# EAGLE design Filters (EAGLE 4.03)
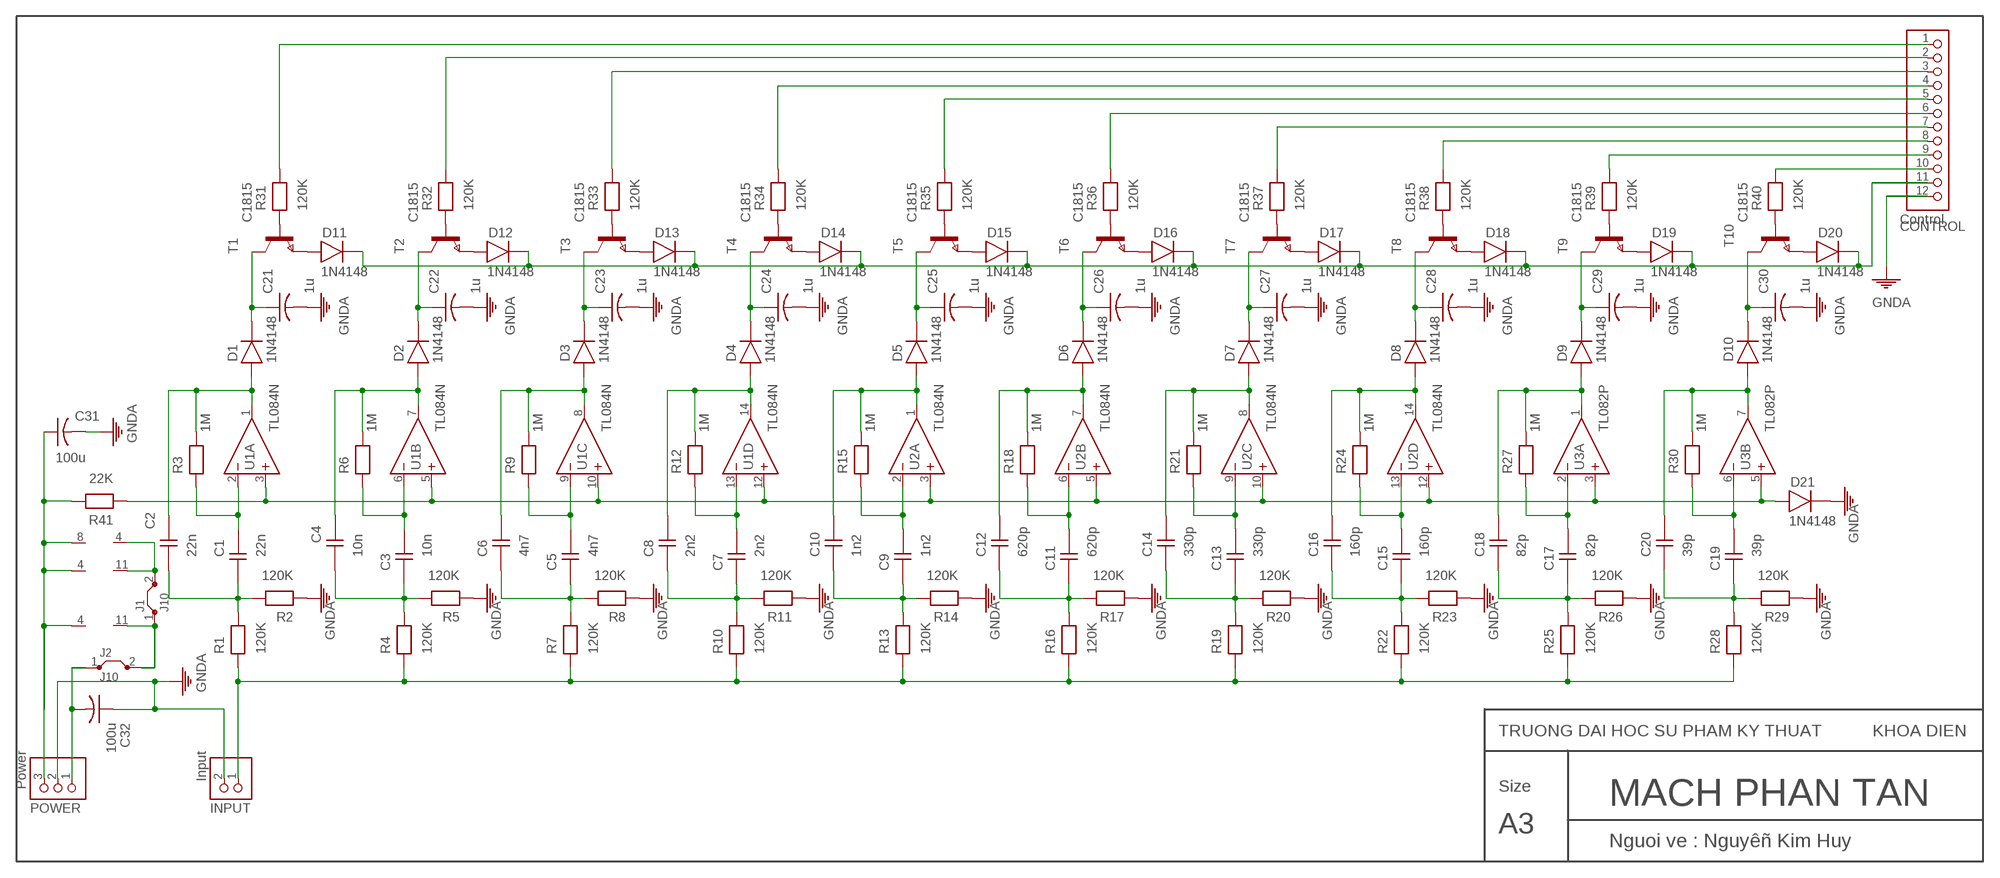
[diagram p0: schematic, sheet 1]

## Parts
C1  22n  CAPNP-5  [C-5]
C2  22n  CAPNP-5  [C-5]
C3  10n  CAPNP-5  [C-5]
C4  10n  CAPNP-5  [C-5]
C5  4n7  CAPNP-5  [C-5]
C6  4n7  CAPNP-5  [C-5]
C7  2n2  CAPNP-5  [C-5]
C8  2n2  CAPNP-5  [C-5]
C9  1n2  CAPNP-5  [C-5]
C10  1n2  CAPNP-5  [C-5]
C11  620p  CAPNP-5  [C-5]
C12  620p  CAPNP-5  [C-5]
C13  330p  CAPNP-5  [C-5]
C14  330p  CAPNP-5  [C-5]
C15  160p  CAPNP-5  [C-5]
C16  160p  CAPNP-5  [C-5]
C17  82p  CAPNP-5  [C-5]
C18  82p  CAPNP-5  [C-5]
C19  39p  CAPNP-5  [C-5]
C20  39p  CAPNP-5  [C-5]
C21  1u  CAP-5  [C-5]
C22  1u  CAP-5  [C-5]
C23  1u  CAP-5  [C-5]
C24  1u  CAP-5  [C-5]
C25  1u  CAP-5  [C-5]
C26  1u  CAP-5  [C-5]
C27  1u  CAP-5  [C-5]
C28  1u  CAP-5  [C-5]
C29  1u  CAP-5  [C-5]
C30  1u  CAP-5  [C-5]
C31  100u  CAP-5@2  [C-5@2]
C32  100u  CAP-5@2  [C-5@2]
CONTROL  Control  PINHD-1X12  [1X12]
D1  1N4148  DIODE-10  [D-10]
D2  1N4148  DIODE-10  [D-10]
D3  1N4148  DIODE-10  [D-10]
D4  1N4148  DIODE-10  [D-10]
D5  1N4148  DIODE-10  [D-10]
D6  1N4148  DIODE-10  [D-10]
D7  1N4148  DIODE-10  [D-10]
D8  1N4148  DIODE-10  [D-10]
D9  1N4148  DIODE-10  [D-10]
D10  1N4148  DIODE-10  [D-10]
D11  1N4148  DIODE-10  [D-10]
D12  1N4148  DIODE-10  [D-10]
D13  1N4148  DIODE-10  [D-10]
D14  1N4148  DIODE-10  [D-10]
D15  1N4148  DIODE-10  [D-10]
D16  1N4148  DIODE-10  [D-10]
D17  1N4148  DIODE-10  [D-10]
D18  1N4148  DIODE-10  [D-10]
D19  1N4148  DIODE-10  [D-10]
D20  1N4148  DIODE-10  [D-10]
D21  1N4148  DIODE-10  [D-10]
INPUT  Input  PINHD-1X2  [1X02]
J1  J10  [07]
J2  J10  [07]
POWER  Power  PINHD-1X3  [1X03]
R1  120K  RESEU-10  [R-10]
R2  120K  RESEU-10  [R-10]
R3  1M  RESEU-10  [R-10]
R4  120K  RESEU-10  [R-10]
R5  120K  RESEU-10  [R-10]
R6  1M  RESEU-10  [R-10]
R7  120K  RESEU-10  [R-10]
R8  120K  RESEU-10  [R-10]
R9  1M  RESEU-10  [R-10]
R10  120K  RESEU-10  [R-10]
R11  120K  RESEU-10  [R-10]
R12  1M  RESEU-10  [R-10]
R13  120K  RESEU-10  [R-10]
R14  120K  RESEU-10  [R-10]
R15  1M  RESEU-10  [R-10]
R16  120K  RESEU-10  [R-10]
R17  120K  RESEU-10  [R-10]
R18  1M  RESEU-10  [R-10]
R19  120K  RESEU-10  [R-10]
R20  120K  RESEU-10  [R-10]
R21  1M  RESEU-10  [R-10]
R22  120K  RESEU-10  [R-10]
R23  120K  RESEU-10  [R-10]
R24  1M  RESEU-10  [R-10]
R25  120K  RESEU-10  [R-10]
R26  120K  RESEU-10  [R-10]
R27  1M  RESEU-10  [R-10]
R28  120K  RESEU-10  [R-10]
R29  120K  RESEU-10  [R-10]
R30  1M  RESEU-10  [R-10]
R31  120K  RESEU-10  [R-10]
R32  120K  RESEU-10  [R-10]
R33  120K  RESEU-10  [R-10]
R34  120K  RESEU-10  [R-10]
R35  120K  RESEU-10  [R-10]
R36  120K  RESEU-10  [R-10]
R37  120K  RESEU-10  [R-10]
R38  120K  RESEU-10  [R-10]
R39  120K  RESEU-10  [R-10]
R40  120K  RESEU-10  [R-10]
R41  22K  RESEU-10  [R-10]
T1  C1815  [TO-92B]
T2  C1815  [TO-92B]
T3  C1815  [TO-92B]
T4  C1815  [TO-92B]
T5  C1815  [TO-92B]
T6  C1815  [TO-92B]
T7  C1815  [TO-92B]
T8  C1815  [TO-92B]
T9  C1815  [TO-92B]
T10  C1815  [TO-92B]
U1  TL084N  [DIL-14]
U2  TL084N  [DIL-14]
U3  TL082P  [DIL-08]

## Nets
GNDA: C21.2 C22.2 C23.2 C24.2 C25.2 C26.2 C27.2 C28.2 C29.2 C30.2 C31.2 C32.1 CONTROL.12 D21.2(K) INPUT.2 POWER.2 R2.1 R5.1 R8.1 R11.1 R14.1 R17.1 R20.1 R23.1 R26.1 R29.1
N$1: C1.2 R3.1 U1.2(A:-IN)
N$2: C1.1 C2.1 R1.2 R2.2
N$3: C3.1 C4.1 R4.2 R5.2
N$4: C9.2 R15.1 U2.2(A:-IN)
N$5: C2.2 D1.1(A) R3.2 U1.1(A:OUT)
N$6: C3.2 R6.1 U1.6(B:-IN)
N$7: C9.1 C10.1 R13.2 R14.2
N$8: C4.2 D2.1(A) R6.2 U1.7(B:OUT)
N$9: D11.1(A) T1.3(E)
N$10: INPUT.1 R1.1 R4.1 R7.1 R10.1 R13.1 R16.1 R19.1 R22.1 R25.1 R28.1
N$11: D21.1(A) R41.1 U1.3(A:+IN) U1.5(B:+IN) U1.10(C:+IN) U1.12(D:+IN) U2.3(A:+IN) U2.5(B:+IN) U2.10(C:+IN) U2.12(D:+IN) U3.3(A:+IN) U3.5(B:+IN)
N$12: C6.2 D3.1(A) R9.2 U1.8(C:OUT)
N$13: C10.2 D5.1(A) R15.2 U2.1(A:OUT)
N$14: C5.2 R9.1 U1.9(C:-IN)
N$15: C19.2 R30.1 U3.6(B:-IN)
N$16: C5.1 C6.1 R7.2 R8.2
N$17: C11.1 C12.1 R16.2 R17.2
N$18: C7.1 C8.1 R10.2 R11.2
N$19: C21.1 D1.2(K) T1.2(C)
N$20: C7.2 R12.1 U1.13(D:-IN)
N$21: C11.2 R18.1 U2.6(B:-IN)
N$22: C8.2 D4.1(A) R12.2 U1.14(D:OUT)
N$23: C20.2 D10.1(A) R30.2 U3.7(B:OUT)
N$24: C12.2 D6.1(A) R18.2 U2.7(B:OUT)
N$25: C22.1 D2.2(K) T2.2(C)
N$26: C13.1 C14.1 R19.2 R20.2
N$27: C23.1 D3.2(K) T3.2(C)
N$28: C13.2 R21.1 U2.9(C:-IN)
N$29: C24.1 D4.2(K) T4.2(C)
N$30: C14.2 D7.1(A) R21.2 U2.8(C:OUT)
N$31: C25.1 D5.2(K) T5.2(C)
N$32: C19.1 C20.1 R28.2 R29.2
N$33: C15.1 C16.1 R22.2 R23.2
N$34: C26.1 D6.2(K) T6.2(C)
N$35: C15.2 R24.1 U2.13(D:-IN)
N$36: C27.1 D7.2(K) T7.2(C)
N$37: C16.2 D8.1(A) R24.2 U2.14(D:OUT)
N$38: C28.1 D8.2(K) T8.2(C)
N$39: C17.1 C18.1 R25.2 R26.2
N$40: C29.1 D9.2(K) T9.2(C)
N$41: C17.2 R27.1 U3.2(A:-IN)
N$42: C30.1 D10.2(K) T10.2(C)
N$43: C18.2 D9.1(A) R27.2 U3.1(A:OUT)
N$44: R31.1 T1.1(B)
N$45: D12.1(A) T2.3(E)
N$46: R32.1 T2.1(B)
N$47: R33.1 T3.1(B)
N$48: CONTROL.11 D11.2(K) D12.2(K) D13.2(K) D14.2(K) D15.2(K) D16.2(K) D17.2(K) D18.2(K) D19.2(K) D20.2(K)
N$49: D13.1(A) T3.3(E)
N$50: R34.1 T4.1(B)
N$51: D14.1(A) T4.3(E)
N$52: R35.1 T5.1(B)
N$53: D15.1(A) T5.3(E)
N$54: R36.1 T6.1(B)
N$55: D16.1(A) T6.3(E)
N$56: D17.1(A) T7.3(E)
N$57: R37.1 T7.1(B)
N$58: R38.1 T8.1(B)
N$59: D18.1(A) T8.3(E)
N$60: R39.1 T9.1(B)
N$61: D19.1(A) T9.3(E)
N$62: R40.1 T10.1(B)
N$63: D20.1(A) T10.3(E)
N$64: CONTROL.10 R40.2
N$65: CONTROL.9 R39.2
N$66: J1.2 U2.11(P:V-) U3.4(P:V-)
N$67: CONTROL.8 R38.2
N$68: CONTROL.7 R37.2
N$69: CONTROL.6 R36.2
N$70: CONTROL.5 R35.2
N$71: CONTROL.4 R34.2
N$72: CONTROL.3 R33.2
N$73: CONTROL.2 R32.2
N$74: CONTROL.1 R31.2
N$75: J1.1 J2.2 U1.11(P:V-)
V+: C31.1 POWER.3 R41.2 U1.4(P:V+) U2.4(P:V+) U3.8(P:V+)
V-: C32.2 J2.1 POWER.1

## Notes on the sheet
- TRUONG DAI HOC SU PHAM KY THUAT | KHOA DIEN
- Size
- MACH PHAN TAN
- A3
- Nguoi ve : Nguyêñ Kim Huy

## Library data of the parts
C1-C20 = DISCRETE:CAPNP-5
C21-C30 = DISCRETE:CAP-5
C31 C32 = DISCRETE:CAP-5@2
CONTROL = PINHEAD:PINHD-1X12
D1-D21 = DISCRETE:DIODE-10
INPUT = PINHEAD:PINHD-1X2
J1 J2 = JUMPER:J10
POWER = PINHEAD:PINHD-1X3
R1-R41 = DISCRETE:RESEU-10
T1-T10 = NPN:C1815
U1 U2 = LINEAR:TL084N
U3 = LINEAR:TL082P

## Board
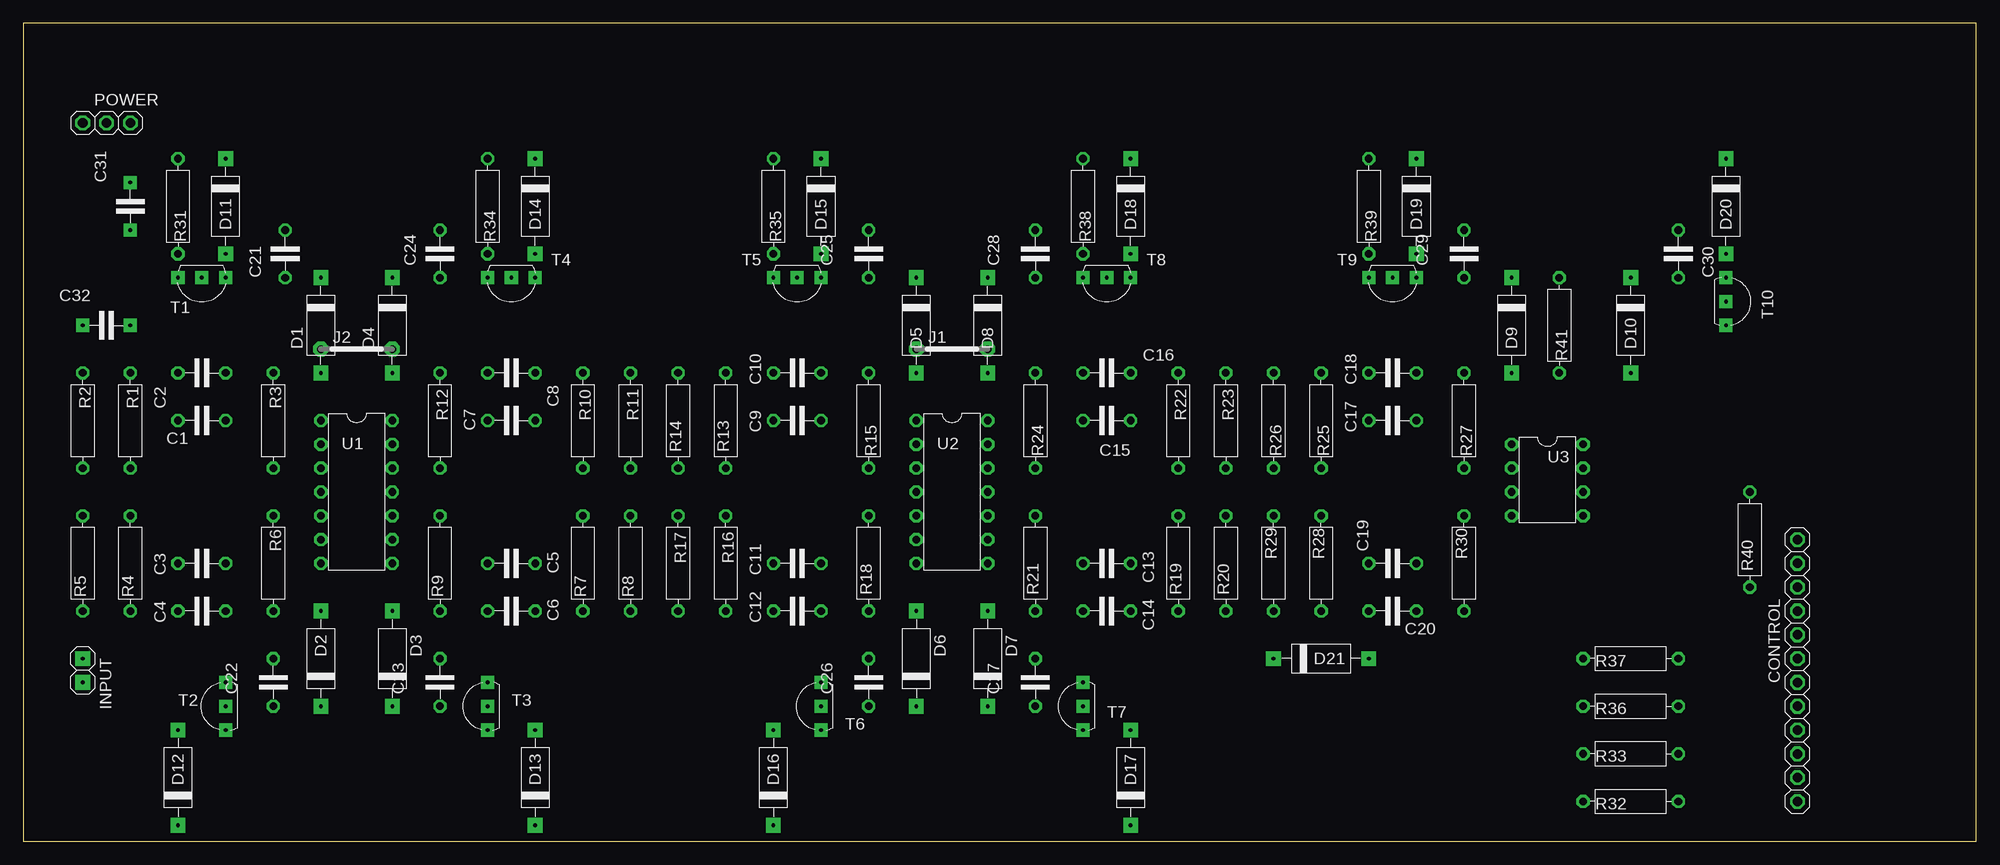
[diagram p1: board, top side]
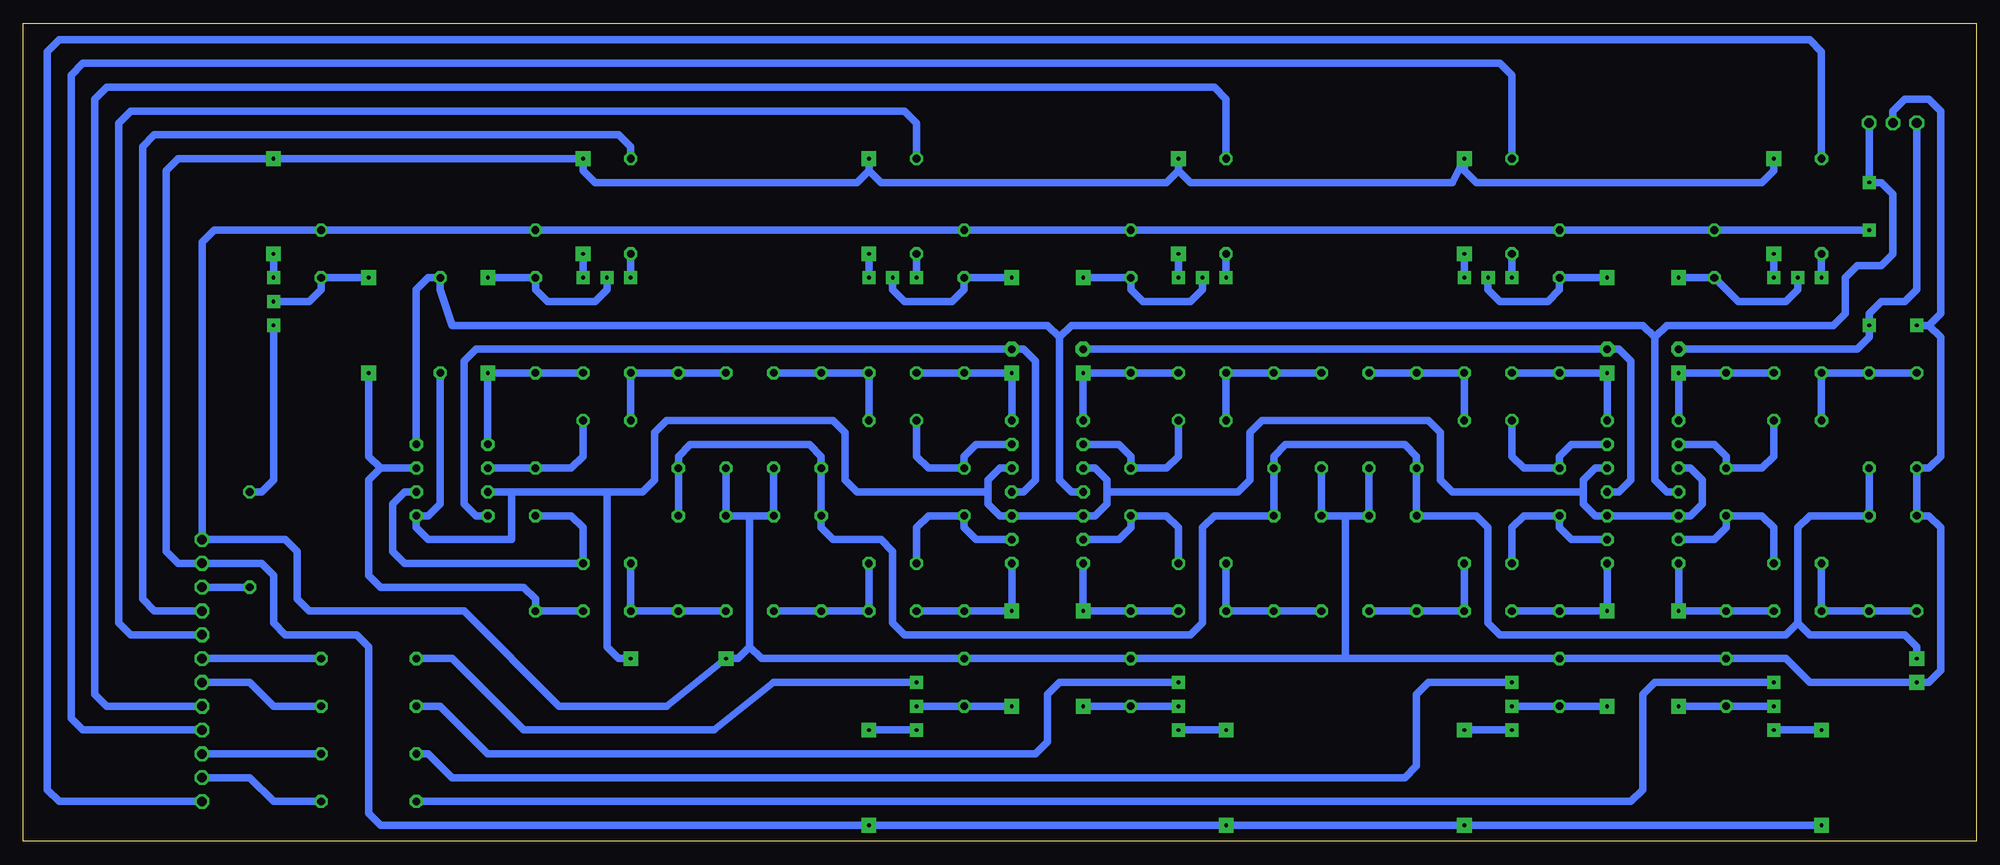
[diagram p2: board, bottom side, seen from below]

Size 208.25 x 87.27 mm. Coordinates in mm from the lower left corner, seen from the top.
Outline: 0,0 208.25,0 208.25,87.27 0,87.27 0,0
Copper layers used: Bottom

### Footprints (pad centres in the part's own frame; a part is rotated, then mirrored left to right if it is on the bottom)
C-5 = drill 0.813 pad 1.397 octagon: 1 -2.54,0; 2 2.54,0
C-5@2 = drill 0.406 pad 1.397 square: 1 -2.54,0; 2 2.54,0
1X12 = drill 1.016 pad 1.575 octagon: 1 -13.97,0; 2 -11.43,0; 3 -8.89,0; 4 -6.35,0; 5 -3.81,0; 6 -1.27,0; 7 1.27,0; 8 3.81,0; 9 6.35,0; 10 8.89,0; 11 11.43,0; 12 13.97,0
D-10 = drill 0.406 pad 1.575 square: 1 -5.08,0; 2 5.08,0
1X02 = drill 0.406 pad 1.575 square: 1 -1.27,0; 2 1.27,0
07 = drill 0.813 pad 1.6 octagon: 1 -3.81,0; 2 3.81,0
1X03 = drill 1.016 pad 1.575 octagon: 1 -2.54,0; 2 0,0; 3 2.54,0
R-10 = drill 0.813 pad 1.397 octagon: 1 -5.08,0; 2 5.08,0
TO-92B = drill 0.406 pad 1.397 square: 1 2.54,0; 2 0,0; 3 -2.54,0
DIL-14 = drill 0.813 pad 1.397 octagon: 1 -7.62,-3.81; 2 -5.08,-3.81; 3 -2.54,-3.81; 4 0,-3.81; 5 2.54,-3.81; 6 5.08,-3.81; 7 7.62,-3.81; 8 7.62,3.81; 9 5.08,3.81; 10 2.54,3.81; 11 0,3.81; 12 -2.54,3.81; 13 -5.08,3.81; 14 -7.62,3.81
DIL-08 = drill 0.813 pad 1.397 octagon: 1 -3.81,-3.81; 2 -1.27,-3.81; 3 1.27,-3.81; 4 3.81,-3.81; 5 3.81,3.81; 6 1.27,3.81; 7 -1.27,3.81; 8 -3.81,3.81

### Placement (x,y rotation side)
C1  19.02,44.91 0 top
C2  19.02,49.99 0 top
C3  19.02,29.67 0 top
C4  19.02,24.59 0 top
C5  52.04,29.67 180 top
C6  52.04,24.59 180 top
C7  52.04,44.91 180 top
C8  52.04,49.99 180 top
C9  82.52,44.91 0 top
C10  82.52,49.99 0 top
C11  82.52,29.67 0 top
C12  82.52,24.59 0 top
C13  115.54,29.67 180 top
C14  115.54,24.59 180 top
C15  115.54,44.91 180 top
C16  115.54,49.99 180 top
C17  146.02,44.91 0 top
C18  146.02,49.99 0 top
C19  146.02,29.67 0 top
C20  146.02,24.59 0 top
C21  27.91,62.69 90 top
C22  26.64,16.97 90 top
C23  44.42,16.97 90 top
C24  44.42,62.69 90 top
C25  90.14,62.69 90 top
C26  90.14,16.97 90 top
C27  107.92,16.97 90 top
C28  107.92,62.69 90 top
C29  153.64,62.69 90 top
C30  176.5,62.69 90 top
C31  11.4,67.77 270 top
C32  8.86,55.07 0 top
CONTROL  189.2,18.24 90 top
D1  31.72,55.07 90 top
D2  31.72,19.51 270 top
D3  39.34,19.51 270 top
D4  39.34,55.07 90 top
D5  95.22,55.07 90 top
D6  95.22,19.51 270 top
D7  102.84,19.51 270 top
D8  102.84,55.07 90 top
D9  158.72,55.07 90 top
D10  171.42,55.07 90 top
D11  21.56,67.77 90 top
D12  16.48,6.81 270 top
D13  54.58,6.81 270 top
D14  54.58,67.77 90 top
D15  85.06,67.77 90 top
D16  79.98,6.81 270 top
D17  118.08,6.81 270 top
D18  118.08,67.77 90 top
D19  148.56,67.77 90 top
D20  181.58,67.77 90 top
D21  138.4,19.51 180 top
INPUT  6.32,18.24 270 top
J1  99.03,52.53 0 top
J2  35.53,52.53 0 top
POWER  8.86,76.66 0 top
R1  11.4,44.91 90 top
R2  6.32,44.91 90 top
R3  26.64,44.91 90 top
R4  11.4,29.67 270 top
R5  6.32,29.67 270 top
R6  26.64,29.67 270 top
R7  59.66,29.67 270 top
R8  64.74,29.67 270 top
R9  44.42,29.67 270 top
R10  59.66,44.91 90 top
R11  64.74,44.91 90 top
R12  44.42,44.91 90 top
R13  74.9,44.91 90 top
R14  69.82,44.91 90 top
R15  90.14,44.91 90 top
R16  74.9,29.67 270 top
R17  69.82,29.67 270 top
R18  90.14,29.67 270 top
R19  123.16,29.67 270 top
R20  128.24,29.67 270 top
R21  107.92,29.67 270 top
R22  123.16,44.91 90 top
R23  128.24,44.91 90 top
R24  107.92,44.91 90 top
R25  138.4,44.91 90 top
R26  133.32,44.91 90 top
R27  153.64,44.91 90 top
R28  138.4,29.67 270 top
R29  133.32,29.67 270 top
R30  153.64,29.67 270 top
R31  16.48,67.77 90 top
R32  171.42,4.27 0 top
R33  171.42,9.35 0 top
R34  49.5,67.77 90 top
R35  79.98,67.77 90 top
R36  171.42,14.43 0 top
R37  171.42,19.51 0 top
R38  113,67.77 90 top
R39  143.48,67.77 90 top
R40  184.12,32.21 270 top
R41  163.8,55.07 90 top
T1  19.02,60.15 180 top
T2  21.56,14.43 90 top
T3  49.5,14.43 90 top
T4  52.04,60.15 180 top
T5  82.52,60.15 180 top
T6  85.06,14.43 90 top
T7  113,14.43 90 top
T8  115.54,60.15 180 top
T9  146.02,60.15 180 top
T10  181.58,57.61 270 top
U1  35.53,37.29 270 top
U2  99.03,37.29 270 top
U3  162.53,38.56 270 top

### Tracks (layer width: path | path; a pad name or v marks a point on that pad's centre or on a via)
GNDA
  Bottom 0.813: R11.1 R8.1 67.28,34.75 | R17.1 R14.1 R17.1 | R23.1 R20.1 130.78,34.75 | R26.1 R29.1 130.78,34.75 | 67.28,34.75 R17.1 | 130.78,20.78 130.78,34.75 | 130.78,20.78 129.51,19.51 C27.2 C26.2 67.28,19.51 | 67.28,19.51 67.28,34.75 | 67.28,19.51 C23.2 C22.2 20.29,19.51 17.75,16.97 INPUT.2 5.05,16.97 3.78,18.24 3.78,33.48 5.05,34.75 R5.1 R2.1 5.05,39.83 3.78,41.1 3.78,53.8 5.05,55.07 | 130.78,20.78 132.05,19.51 D21.2 139.67,14.43 151.1,14.43 161.26,24.59 177.77,24.59 179.04,25.86 179.04,30.94 180.31,32.21 CONTROL.12 189.2,63.96 187.93,65.23 C30.2 C29.2 C28.2 C25.2 C24.2 C21.2 C31.2 | POWER.2 8.86,77.93 7.59,79.2 5.05,79.2 3.78,77.93 3.78,56.34 5.05,55.07 | 5.05,55.07 C32.1
N$1
  Bottom 0.813: U1.2 27.91,42.37 26.64,41.1 R3.1 22.83,39.83 21.56,41.1 C1.2
N$2
  Bottom 0.813: C1.1 C2.1 R1.2 R2.2
N$3
  Bottom 0.813: C3.1 C4.1 R4.2 R5.2
N$4
  Bottom 0.813: U2.2 91.41,42.37 90.14,41.1 R15.1 86.33,39.83 85.06,41.1 C9.2
N$5
  Bottom 0.813: C2.2 R3.2 D1.1 U1.1
N$6
  Bottom 0.813: U1.6 27.91,32.21 26.64,33.48 R6.1 22.83,34.75 21.56,33.48 C3.2
N$7
  Bottom 0.813: C9.1 C10.1 R13.2 R14.2
N$8
  Bottom 0.813: C4.2 R6.2 D2.1 U1.7
N$9
  Bottom 0.813: T1.3 D11.1
N$10
  Bottom 0.813: R1.1 R4.1 17.75,34.75 19.02,33.48 19.02,23.32 | R28.1 R25.1 138.4,41.1 137.13,42.37 124.43,42.37 123.16,41.1 R22.1 R19.1 123.16,33.48 121.89,32.21 116.81,32.21 115.54,30.94 115.54,23.32 114.27,22.05 83.79,22.05 82.52,23.32 82.52,33.48 81.25,34.75 R16.1 R13.1 74.9,41.1 73.63,42.37 60.93,42.37 59.66,41.1 R10.1 R7.1 53.31,34.75 52.04,33.48 52.04,23.32 50.77,22.05 20.29,22.05 19.02,23.32 | INPUT.1 6.32,20.78 7.59,22.05 17.75,22.05 19.02,23.32
N$11
  Bottom 0.813: U1.12 40.61,39.83 41.88,38.56 41.88,37.29 | 41.88,37.29 41.88,36.02 40.61,34.75 U1.10 U1.5 30.45,34.75 29.18,36.02 29.18,38.56 30.45,39.83 U1.3 | U2.12 104.11,39.83 105.38,38.56 105.38,37.29 | 105.38,37.29 105.38,36.02 104.11,34.75 U2.10 U2.5 93.95,34.75 92.68,36.02 92.68,37.29 | U2.3 93.95,39.83 92.68,38.56 92.68,37.29 | 156.18,37.29 U3.3 | 156.18,37.29 156.18,32.21 165.07,32.21 166.34,33.48 U3.5 165.07,34.75 163.8,36.02 R41.1 | 105.38,37.29 119.35,37.29 120.62,38.56 120.62,43.64 121.89,44.91 139.67,44.91 140.94,43.64 140.94,38.56 142.21,37.29 146.02,37.29 | 146.02,37.29 156.18,37.29 | 41.88,37.29 55.85,37.29 57.12,38.56 57.12,43.64 58.39,44.91 76.17,44.91 77.44,43.64 77.44,38.56 78.71,37.29 92.68,37.29 | D21.1 144.75,19.51 146.02,20.78 146.02,37.29
N$12
  Bottom 0.813: C6.2 R9.2 D3.1 U1.8
N$13
  Bottom 0.813: C10.2 R15.2 D5.1 U2.1
N$14
  Bottom 0.813: U1.9 43.15,32.21 44.42,33.48 R9.1 48.23,34.75 49.5,33.48 C5.2
N$15
  Bottom 0.813: R30.1 149.83,34.75 148.56,33.48 C19.2 167.61,29.67 168.88,30.94 168.88,36.02 167.61,37.29 U3.6
N$16
  Bottom 0.813: C5.1 C6.1 R7.2 R8.2
N$17
  Bottom 0.813: C11.1 C12.1 R16.2 R17.2
N$18
  Bottom 0.813: C7.1 C8.1 R10.2 R11.2
N$19
  Bottom 0.813: D1.2 C21.1 25.37,57.61 20.29,57.61 19.02,58.88 T1.2
N$20
  Bottom 0.813: U1.13 43.15,42.37 44.42,41.1 R12.1 48.23,39.83 49.5,41.1 C7.2
N$21
  Bottom 0.813: U2.6 91.41,32.21 90.14,33.48 R18.1 86.33,34.75 85.06,33.48 C11.2
N$22
  Bottom 0.813: C8.2 R12.2 D4.1 U1.14
N$23
  Bottom 0.813: 170.15,39.83 171.42,41.1 D10.1 | 170.15,39.83 171.42,38.56 171.42,28.4 170.15,27.13 154.91,27.13 153.64,25.86 R30.2 C20.2 | 170.15,39.83 U3.7
N$24
  Bottom 0.813: C12.2 R18.2 D6.1 U2.7
N$25
  Bottom 0.813: D2.2 C22.1 T2.2
N$26
  Bottom 0.813: C13.1 C14.1 R19.2 R20.2
N$27
  Bottom 0.813: D3.2 C23.1 T3.2
N$28
  Bottom 0.813: U2.9 106.65,32.21 107.92,33.48 R21.1 111.73,34.75 113,33.48 C13.2
N$29
  Bottom 0.813: D4.2 C24.1 44.42,58.88 45.69,57.61 50.77,57.61 52.04,58.88 T4.2
N$30
  Bottom 0.813: C14.2 R21.2 D7.1 U2.8
N$31
  Bottom 0.813: D5.2 C25.1 90.14,58.88 88.87,57.61 83.79,57.61 82.52,58.88 T5.2
N$32
  Bottom 0.813: R29.2 R28.2 C20.1 C19.1
N$33
  Bottom 0.813: C15.1 C16.1 R22.2 R23.2
N$34
  Bottom 0.813: D6.2 C26.1 T6.2
N$35
  Bottom 0.813: C15.2 113,41.1 111.73,39.83 R24.1 107.92,41.1 106.65,42.37 U2.13
N$36
  Bottom 0.813: D7.2 C27.1 T7.2
N$37
  Bottom 0.813: C16.2 R24.2 D8.1 U2.14
N$38
  Bottom 0.813: D8.2 C28.1 107.92,58.88 109.19,57.61 114.27,57.61 115.54,58.88 T8.2
N$39
  Bottom 0.813: R26.2 R25.2 C18.1 C17.1
N$40
  Bottom 0.813: D9.2 C29.1 153.64,58.88 152.37,57.61 147.29,57.61 146.02,58.88 T9.2
N$41
  Bottom 0.813: U3.2 R27.1 149.83,39.83 148.56,41.1 C17.2
N$42
  Bottom 0.813: D10.2 C30.1 176.5,58.88 177.77,57.61 T10.2
N$43
  Bottom 0.813: C18.2 R27.2 D9.1 U3.1
N$44
  Bottom 0.813: T1.1 R31.1
N$45
  Bottom 0.813: D12.1 T2.3
N$46
  Bottom 0.813: T2.1 34.26,16.97 35.53,15.7 35.53,5.54 36.8,4.27 R32.1
N$47
  Bottom 0.813: T3.1 58.39,16.97 59.66,15.7 59.66,8.08 60.93,6.81 162.53,6.81 165.07,9.35 R33.1
N$48
  Bottom 0.813: D12.2 D13.2 D16.2 D17.2 170.15,1.73 171.42,3 171.42,20.78 172.69,22.05 180.31,22.05 181.58,23.32 181.58,28.4 182.85,29.67 CONTROL.11 191.74,29.67 193.01,30.94 193.01,71.58 191.74,72.85 D20.2 D19.2 148.56,71.58 147.29,70.31 119.35,70.31 118.08,71.58 | 118.08,71.58 D18.2 | 118.08,71.58 116.81,70.31 86.33,70.31 85.06,71.58 | 85.06,71.58 D15.2 | 85.06,71.58 83.79,70.31 55.85,70.31 D14.2 54.58,71.58 53.31,70.31 22.83,70.31 21.56,71.58 D11.2
N$49
  Bottom 0.813: T3.3 D13.1
N$50
  Bottom 0.813: T4.1 R34.1
N$51
  Bottom 0.813: T4.3 D14.1
N$52
  Bottom 0.813: T5.1 R35.1
N$53
  Bottom 0.813: T5.3 D15.1
N$54
  Bottom 0.813: T6.1 97.76,16.97 99.03,15.7 99.03,10.62 100.3,9.35 158.72,9.35 163.8,14.43 R36.1
N$55
  Bottom 0.813: D16.1 T6.3
N$56
  Bottom 0.813: T7.3 D17.1
N$57
  Bottom 0.813: T7.1 128.24,16.97 134.59,11.89 154.91,11.89 162.53,19.51 R37.1
N$58
  Bottom 0.813: T8.1 R38.1
N$59
  Bottom 0.813: T8.3 D18.1
N$60
  Bottom 0.813: T9.1 R39.1
N$61
  Bottom 0.813: T9.3 D19.1
N$62
  Bottom 0.813: R40.1 182.85,37.29 181.58,38.56 T10.1
N$63
  Bottom 0.813: T10.3 D20.1
N$64
  Bottom 0.813: R40.2 CONTROL.10
N$65
  Bottom 0.813: R39.2 143.48,74.12 144.75,75.39 194.28,75.39 195.55,74.12 195.55,25.86 194.28,24.59 CONTROL.9
N$66
  Bottom 0.813: U3.4 159.99,34.75 161.26,36.02 161.26,51.26 159.99,52.53 J1.2 101.57,52.53 100.3,51.26 100.3,38.56 101.57,37.29 U2.11
N$67
  Bottom 0.813: R38.2 113,76.66 114.27,77.93 196.82,77.93 198.09,76.66 198.09,23.32 196.82,22.05 CONTROL.8
N$68
  Bottom 0.813: R37.2 CONTROL.7
N$69
  Bottom 0.813: R36.2 181.58,14.43 184.12,16.97 CONTROL.6
N$70
  Bottom 0.813: R35.2 79.98,79.2 81.25,80.47 199.36,80.47 200.63,79.2 200.63,15.7 199.36,14.43 CONTROL.5
N$71
  Bottom 0.813: R34.2 49.5,81.74 50.77,83.01 201.9,83.01 203.17,81.74 203.17,13.16 201.9,11.89 CONTROL.4
N$72
  Bottom 0.813: R33.2 CONTROL.3
N$73
  Bottom 0.813: R32.2 181.58,4.27 184.12,6.81 CONTROL.2
N$74
  Bottom 0.813: R31.2 16.48,84.28 17.75,85.55 204.44,85.55 205.71,84.28 205.71,5.54 204.44,4.27 CONTROL.1
N$75
  Bottom 0.813: U1.11 38.07,37.29 36.8,38.56 36.8,51.26 38.07,52.53 J2.2 J1.1
V+
  Bottom 0.813: U3.8 166.34,58.88 165.07,60.15 R41.2 163.8,58.88 162.53,55.07 99.03,55.07 97.76,53.8 | U2.4 96.49,37.29 97.76,38.56 97.76,53.8 | 97.76,53.8 96.49,55.07 35.53,55.07 34.26,53.8 | 34.26,53.8 34.26,38.56 32.99,37.29 U1.4 | POWER.3 C31.1 10.13,70.31 8.86,69.04 8.86,62.69 10.13,61.42 12.67,61.42 13.94,60.15 13.94,56.34 15.21,55.07 32.99,55.07 34.26,53.8
V-
  Bottom 0.813: POWER.1 6.32,58.88 7.59,57.61 10.13,57.61 11.4,56.34 C32.2 11.4,53.8 12.67,52.53 J2.1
